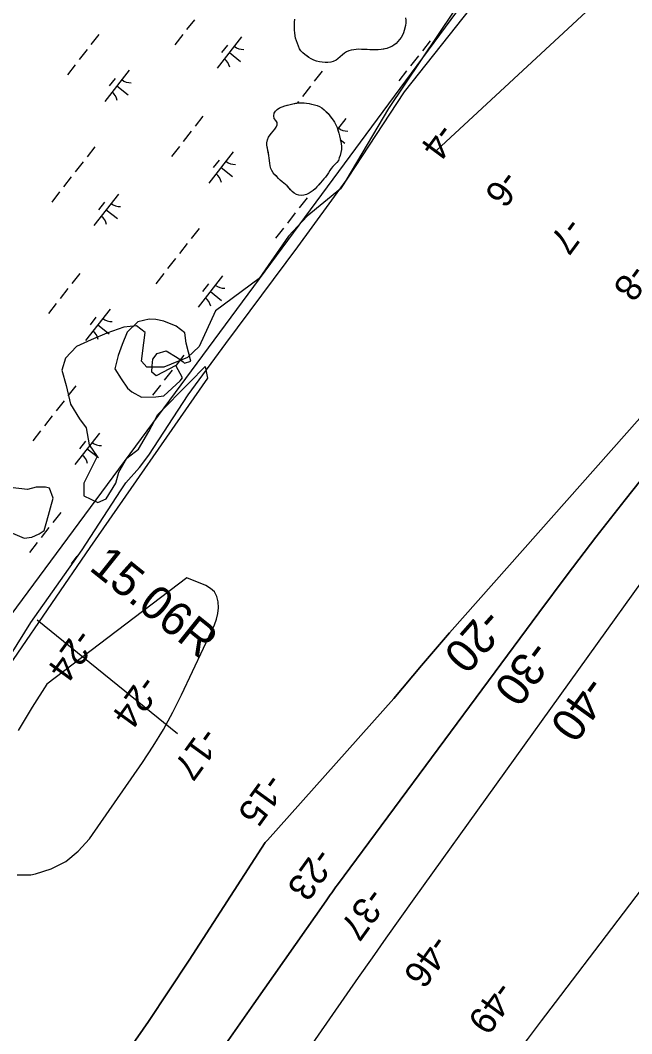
# Model space of a CAD drawing. Extents: x 3896831 to 3918110, y 171006 to 193349.
# Drawn here: x 3903450 to 3904219, y 175445 to 176718 of the extents above; entities that cross this region are included whole.
import ezdxf

# ---------------------------------------------------------------- set-up
doc = ezdxf.new("R2010")
doc.units = 0
for name, color, linetype in [('V-LEVE-TOET', 7, 'Continuous'), ('V-RIVR-EDGE', 7, 'Continuous'), ('V-RIVR-RANG', 7, 'Continuous'), ('V-RRAP-FSHR', 7, 'Continuous'), ('V-STRM-FMON', 7, 'Continuous'), ('V-TOPO-DPTH', 7, 'Continuous'), ('V-TOPO-MAJR', 7, 'Continuous'), ('V-TOPO-MINR', 7, 'Continuous'), ('V-TOPO-MINR-IDEN', 7, 'Continuous'), ('V-TOPO-SHOR', 7, 'Continuous'), ('V-WETL-SWMP', 7, 'Continuous')]:
    doc.layers.add(name, color=color, linetype=linetype)

msp = doc.modelspace()

# ---------------------------------------------------------------- linework, layer by layer
at = {"layer": 'V-LEVE-TOET'}
msp.add_line((3903471.6, 175964.8), (3903647.7, 175822), dxfattribs=at)
at = {"layer": 'V-RIVR-EDGE'}
msp.add_lwpolyline([(3904062.7, 176792.1), (3903932.6, 176627.7), (3903852.7, 176505.9), (3903810.9, 176471.6), (3903787.6, 176446.5), (3903750.5, 176393.5), (3903695.7, 176352.6), (3903675.2, 176308), (3903660.3, 176294.1), (3903630.6, 176282), (3903609.2, 176282), (3903602.7, 176289.4), (3903605.5, 176312.7), (3903607.4, 176325.7), (3903596.2, 176334), (3903580.4, 176332.2), (3903559.1, 176324.7), (3903539.5, 176316.4), (3903521, 176308), (3903507, 176293.1), (3903502.4, 176278.3), (3903508, 176258.8), (3903513.5, 176235.5), (3903524.7, 176216.9), (3903533, 176205.8), (3903536.8, 176184.4), (3903547, 176169.6), (3903530.3, 176136.1), (3903530.3, 176120.3), (3903547.9, 176111.9), (3903558.1, 176116.6), (3903570.2, 176136.1), (3903573.9, 176150), (3903584.1, 176167.7), (3903599, 176178.9), (3903612, 176201.2), (3903623.2, 176222.5), (3903663.1, 176262.5), (3903682.6, 176282.9), (3903685.4, 176268.1), (3903537.7, 176055.3), (3903392.7, 175844.3)], dxfattribs=at)
at = {"layer": 'V-RRAP-FSHR'}
msp.add_lwpolyline([(3903099, 175512.1), (3904431.1, 177312.9), (3905197.8, 178658.5), (3906088.4, 179617.4), (3906806.7, 180565.1), (3907065.2, 181039), (3907795.1, 181990.7)], dxfattribs=at)
at = {"layer": 'V-TOPO-DPTH'}
for points in [[(3903455, 175243.5), (3903504.5, 175309.5), (3903558.8, 175384.3), (3903611.2, 175460.3), (3903662.4, 175537.2), (3903758.1, 175684.8), (3903760.9, 175687.9), (3903920, 175865.9), (3903954.5, 175907.3), (3903989.7, 175948.1), (3904284.6, 176280.7)], [(3904247.5, 176161.7), (3904210.5, 176115.2), (3904173.9, 176068.3), (3904137.8, 176021), (3904102.1, 175973.5), (3903848.9, 175631.8), (3903847, 175629.3), (3903845.2, 175626.8), (3903843.4, 175624.3), (3903841.7, 175621.8), (3903839.9, 175619.2), (3903838.2, 175616.7), (3903836.4, 175614.2), (3903834.7, 175611.6), (3903744, 175482.2), (3903696.7, 175415.2), (3903649, 175348.4), (3903600.7, 175282), (3903552.1, 175215.9), (3903530.3, 175186.6)], [(3903530.3, 175186.6), (3903552.1, 175215.9), (3903600.7, 175282), (3903649, 175348.4), (3903696.7, 175415.2), (3903744, 175482.2), (3903834.7, 175611.6), (3903836.4, 175614.2), (3903838.2, 175616.7), (3903839.9, 175619.2), (3903841.7, 175621.8), (3903843.4, 175624.3), (3903845.2, 175626.8), (3903847, 175629.3), (3903848.9, 175631.8), (3904102.1, 175973.5), (3904137.8, 176021), (3904173.9, 176068.3), (3904210.5, 176115.2), (3904247.5, 176161.7)], [(3904255.6, 176046.2), (3903945, 175614.1), (3903927.4, 175589.5), (3903909.8, 175564.8), (3903892.4, 175540), (3903875.1, 175515.2), (3903774.4, 175370.4), (3903726.9, 175302.4), (3903679.2, 175234.5), (3903631.3, 175166.8), (3903605.2, 175130.1)], [(3904255.6, 176046.2), (3903945, 175614.1), (3903927.4, 175589.5), (3903909.8, 175564.8), (3903892.4, 175540), (3903875.1, 175515.2), (3903774.4, 175370.4), (3903726.9, 175302.4), (3903679.2, 175234.5), (3903631.3, 175166.8), (3903605.2, 175130.1)], [(3903446.5, 175644.4), (3903463.4, 175644.4), (3903469.2, 175645.5), (3903489.2, 175651.9), (3903507.5, 175661), (3903523.1, 175674), (3903537.1, 175689.7), (3903603.8, 175785.3), (3903617.4, 175805.9), (3903630.3, 175826.8), (3903642, 175848.5), (3903653, 175870.5), (3903694.3, 175958.5), (3903696.8, 175965.4), (3903698.6, 175972.5), (3903699.3, 175979.7), (3903699.1, 175987.1), (3903697.2, 175993.8), (3903694.2, 175999.6), (3903689.5, 176004.1), (3903683.6, 176007.7), (3903659.5, 176017.4), (3903483.6, 175883.8)], [(3903483.6, 175883.8), (3903465.1, 175854.9), (3903447.6, 175825.4)]]:
    msp.add_lwpolyline(points, dxfattribs=at)
at = {"layer": 'V-TOPO-MAJR'}
msp.add_lwpolyline([(3904246.5, 175647), (3904193.6, 175577.1), (3904122.8, 175484.1), (3904105.1, 175460.8), (3904087.4, 175437.6), (3904069.6, 175414.4), (3904051.8, 175391.3), (3903932.4, 175236.1), (3903882.7, 175172), (3903832.8, 175108.1), (3903782.5, 175044.5), (3903758.5, 175014.3)], dxfattribs=at)
at = {"layer": 'V-TOPO-MINR'}
for points in [[(3904260.2, 176827.7), (3904201.3, 176765.7), (3903973.7, 176554.7)], [(3904284.6, 176280.7), (3903989.7, 175948.1), (3903954.5, 175907.3), (3903920, 175865.9), (3903760.9, 175687.9), (3903758.1, 175684.8), (3903662.4, 175537.2), (3903611.2, 175460.3), (3903558.8, 175384.3), (3903504.5, 175309.5), (3903455, 175243.5)], [(3904247.5, 176161.7), (3904210.5, 176115.2), (3904173.9, 176068.3), (3904137.8, 176021), (3904102.1, 175973.5), (3903848.9, 175631.8), (3903847, 175629.3), (3903845.2, 175626.8), (3903843.4, 175624.3), (3903841.7, 175621.8), (3903839.9, 175619.2), (3903838.2, 175616.7), (3903836.4, 175614.2), (3903834.7, 175611.6), (3903744, 175482.2), (3903696.7, 175415.2), (3903649, 175348.4), (3903600.7, 175282), (3903552.1, 175215.9), (3903530.3, 175186.6)], [(3904255.6, 176046.2), (3903945, 175614.1), (3903927.4, 175589.5), (3903909.8, 175564.8), (3903892.4, 175540), (3903875.1, 175515.2), (3903774.4, 175370.4), (3903726.9, 175302.4), (3903679.2, 175234.5), (3903631.3, 175166.8), (3903605.2, 175130.1)], [(3903446.5, 175644.4), (3903463.4, 175644.4), (3903469.2, 175645.5), (3903489.2, 175651.9), (3903507.5, 175661), (3903523.1, 175674), (3903537.1, 175689.7), (3903603.8, 175785.3), (3903617.4, 175805.9), (3903630.3, 175826.8), (3903642, 175848.5), (3903653, 175870.5), (3903694.3, 175958.5), (3903696.8, 175965.4), (3903698.6, 175972.5), (3903699.3, 175979.7), (3903699.1, 175987.1), (3903697.2, 175993.8), (3903694.2, 175999.6), (3903689.5, 176004.1), (3903683.6, 176007.7), (3903659.5, 176017.4), (3903483.6, 175883.8)], [(3903483.6, 175883.8), (3903465.1, 175854.9), (3903447.6, 175825.4)]]:
    msp.add_lwpolyline(points, dxfattribs=at)
at = {"layer": 'V-TOPO-SHOR'}
for points in [[(3903797.6, 176691.7), (3903796.4, 176695), (3903795.7, 176698.3), (3903795.5, 176701.7), (3903795.1, 176705.2), (3903795, 176708.3), (3903794.8, 176711.7), (3903795, 176715.5), (3903795.4, 176718.9)], [(3903934.6, 176720.7), (3903934.8, 176717.6), (3903934.8, 176714.3), (3903934.4, 176711.2), (3903933.6, 176708), (3903932.9, 176705), (3903931.9, 176702), (3903930.6, 176698.8), (3903929, 176696.2), (3903927.1, 176693.5), (3903924.7, 176690.9), (3903922.6, 176688.5), (3903920, 176686.3), (3903917.3, 176684.8), (3903914.1, 176683.4), (3903911, 176682.3), (3903907.1, 176681.5), (3903903.9, 176680.9), (3903900.1, 176680.7), (3903897, 176680.6), (3903893.3, 176680.6), (3903889.7, 176680.6), (3903886.4, 176680.8), (3903883, 176680.9), (3903879.3, 176681.1), (3903876, 176681.2), (3903872.6, 176681), (3903869.4, 176680.6), (3903866.3, 176680.1), (3903863.3, 176679.1), (3903860.4, 176677.9), (3903857.8, 176676.3), (3903855.1, 176674.3)], [(3903855.1, 176674.3), (3903852.4, 176671.8), (3903849.6, 176669.3), (3903847.2, 176667.5), (3903843.7, 176665.8), (3903840.7, 176665), (3903836.8, 176664.6), (3903833.7, 176664.5), (3903829.6, 176664.9), (3903826.3, 176665.5), (3903822.5, 176666.5), (3903819.3, 176667.6), (3903816, 176669.1), (3903813.1, 176670.8), (3903810.4, 176672.8), (3903807.9, 176674.8), (3903805.3, 176676.9), (3903803.1, 176679.2), (3903801.4, 176681.6), (3903797.6, 176691.7)], [(3903779.5, 176514.9), (3903777.1, 176517), (3903774.9, 176519.1), (3903772.6, 176521.3), (3903770.3, 176523.4), (3903768.3, 176526), (3903766.5, 176528.8), (3903765.2, 176531.6), (3903764.4, 176534.7), (3903763.9, 176538.1), (3903763.6, 176541.4), (3903763.3, 176544.5), (3903762.8, 176548), (3903762.2, 176551.2), (3903761.5, 176554.1), (3903760.8, 176557.5), (3903760.2, 176560.6), (3903760.3, 176563.8), (3903760.9, 176567.3), (3903762.4, 176570.8), (3903764.2, 176573.7), (3903766.1, 176576), (3903768.2, 176578.3), (3903770.2, 176580.8), (3903771.8, 176583.4), (3903773, 176586.2), (3903773, 176589.3), (3903771.4, 176591.9), (3903769.5, 176594.5), (3903768.9, 176597.6), (3903769.5, 176600.8), (3903771.1, 176603.4), (3903773.3, 176605.7), (3903776, 176607.5), (3903779.6, 176609), (3903782.8, 176610.2), (3903785.7, 176611), (3903789.3, 176612), (3903792.8, 176612.8), (3903796.3, 176613.4), (3903800.3, 176614), (3903803.6, 176614.1), (3903806.9, 176614), (3903810.2, 176613.6), (3903813.2, 176613.1), (3903816.3, 176612.4), (3903820.1, 176611.5), (3903823.3, 176610.5), (3903826.3, 176609.3), (3903829.3, 176607.5), (3903832.2, 176605.3), (3903834.8, 176602.8), (3903837.1, 176600.6), (3903839.3, 176597.8), (3903841.6, 176594.7), (3903843.5, 176592.3), (3903845.4, 176589.5), (3903847.1, 176586.2), (3903848.4, 176582.9), (3903849.5, 176579.6), (3903850.7, 176575.8), (3903851.6, 176572.4), (3903852.2, 176569.1), (3903852.8, 176566.1), (3903853.4, 176562.8), (3903853.9, 176559.3), (3903853.9, 176555.4), (3903853.1, 176551.4), (3903852.4, 176547.9), (3903851.3, 176544.7), (3903850.1, 176541.7), (3903848.2, 176539), (3903845.7, 176536.6), (3903843.3, 176534.1), (3903840.9, 176531.4), (3903839.2, 176528.9), (3903837.6, 176526.1), (3903835.8, 176523.5), (3903833.8, 176520.7), (3903831.9, 176518.4), (3903829.9, 176515.9), (3903827.7, 176513.4), (3903825.5, 176511.1), (3903823.1, 176508.5), (3903820.9, 176506.1), (3903818.4, 176503.9), (3903816.1, 176502), (3903813.4, 176500.3), (3903809.9, 176498.7), (3903806.7, 176497.9), (3903803.6, 176497.5), (3903800.5, 176497.8), (3903797.5, 176498.7), (3903794.6, 176500.5), (3903792.1, 176502.6), (3903789.8, 176504.9), (3903787.8, 176507.2), (3903785.6, 176509.6), (3903779.5, 176514.9)]]:
    msp.add_lwpolyline(points, dxfattribs=at)
for points in [[(3903664.6, 176289.7), (3903658.6, 176311.9), (3903657.1, 176324.9), (3903646.2, 176333.4), (3903630.6, 176339.7), (3903620.5, 176341.8), (3903612.2, 176342.4), (3903597.9, 176339), (3903584.7, 176326), (3903578.3, 176310.4), (3903573.4, 176296.7), (3903568.9, 176279.7), (3903577, 176267.5), (3903585, 176255.4), (3903590.4, 176251.1), (3903602.8, 176244.4), (3903620.8, 176244.9), (3903630.5, 176246.1), (3903651.2, 176265), (3903654, 176268.7), (3903645.6, 176284.1), (3903620.9, 176271.2), (3903615.4, 176275.5), (3903616.1, 176283.8), (3903616.7, 176292.1), (3903622.4, 176299.3), (3903633.5, 176302.3), (3903647.6, 176294.2), (3903654.9, 176288.5), (3903656.7, 176287.1)], [(3903483.7, 176088.7), (3903491.7, 176117.6), (3903486.8, 176130.1), (3903481.8, 176131.2), (3903470.3, 176131.4), (3903459.1, 176128.4), (3903437.5, 176130.7), (3903423.8, 176135.6), (3903414, 176134.4), (3903397.6, 176120.9), (3903398.8, 176111.2), (3903418.8, 176095.6), (3903428.2, 176085.2), (3903437.7, 176074.9), (3903455.1, 176067.1), (3903464.8, 176068.3), (3903474.1, 176072.7), (3903480.2, 176076.8)]]:
    msp.add_lwpolyline(points, close=True, dxfattribs=at)
at = {"layer": 'V-WETL-SWMP'}
for p, q in [((3903913.5, 176606.7), (3903995.8, 176728.9)), ((3903669.2, 176718.4), (3903659.3, 176705.9)), ((3903794.8, 176711.7), (3903795, 176715.5)), ((3903795.1, 176705.2), (3903794.8, 176711.7)), ((3903795, 176715.5), (3903795.4, 176718.9)), ((3903934.4, 176711.2), (3903932.9, 176705)), ((3903934.8, 176714.3), (3903934.4, 176711.2)), ((3903934.6, 176720.7), (3903934.8, 176717.6)), ((3903934.8, 176717.6), (3903934.8, 176714.3)), ((3903548.9, 176699.7), (3903539, 176687.1)), ((3903654.4, 176699.6), (3903644.5, 176687)), ((3903795.5, 176701.7), (3903795.1, 176705.2)), ((3903795.7, 176698.3), (3903795.5, 176701.7)), ((3903796.4, 176695), (3903795.7, 176698.3)), ((3903930.6, 176698.8), (3903929, 176696.2)), ((3903931.9, 176702), (3903930.6, 176698.8)), ((3903932.9, 176705), (3903931.9, 176702)), ((3903728.5, 176696.8), (3903697.6, 176657.5)), ((3903710.7, 176686.6), (3903703.3, 176677.2)), ((3903797.6, 176691.7), (3903796.4, 176695)), ((3903801.3, 176681.6), (3903797.6, 176691.7)), ((3903917.3, 176684.8), (3903914.1, 176683.4)), ((3903920, 176686.3), (3903917.3, 176684.8)), ((3903922.6, 176688.5), (3903920, 176686.3)), ((3903927.1, 176693.5), (3903922.6, 176688.5)), ((3903929, 176696.2), (3903927.1, 176693.5)), ((3903965.5, 176692), (3903955.7, 176679.4)), ((3903534.1, 176680.8), (3903524.2, 176668.2)), ((3903713.1, 176677.1), (3903727.2, 176666)), ((3903803.1, 176679.2), (3903801.3, 176681.6)), ((3903805.3, 176676.9), (3903803.1, 176679.2)), ((3903807.9, 176674.8), (3903805.3, 176676.9)), ((3903813.1, 176670.8), (3903807.9, 176674.8)), ((3903855.1, 176674.3), (3903849.6, 176669.3)), ((3903857.8, 176676.3), (3903855.1, 176674.3)), ((3903860.4, 176677.9), (3903857.8, 176676.3)), ((3903863.3, 176679.1), (3903860.4, 176677.9)), ((3903866.3, 176680.1), (3903863.3, 176679.1)), ((3903869.4, 176680.6), (3903866.3, 176680.1)), ((3903872.6, 176681), (3903869.4, 176680.6)), ((3903876, 176681.2), (3903872.6, 176681)), ((3903886.4, 176680.8), (3903876, 176681.2)), ((3903889.7, 176680.6), (3903886.4, 176680.8)), ((3903897, 176680.6), (3903889.7, 176680.6)), ((3903903.9, 176680.9), (3903897, 176680.6)), ((3903911, 176682.3), (3903903.9, 176680.9)), ((3903914.1, 176683.4), (3903911, 176682.3)), ((3903950.7, 176673.1), (3903940.9, 176660.5)), ((3903519.3, 176661.9), (3903509.4, 176649.3)), ((3903816, 176669.1), (3903813.1, 176670.8)), ((3903819.3, 176667.6), (3903816, 176669.1)), ((3903822.5, 176666.5), (3903819.3, 176667.6)), ((3903826.3, 176665.5), (3903822.5, 176666.5)), ((3903829.6, 176664.9), (3903826.3, 176665.5)), ((3903833.7, 176664.5), (3903829.6, 176664.9)), ((3903836.8, 176664.6), (3903833.7, 176664.5)), ((3903840.7, 176665), (3903836.8, 176664.6)), ((3903843.7, 176665.8), (3903840.7, 176665)), ((3903847.2, 176667.5), (3903843.7, 176665.8)), ((3903849.6, 176669.3), (3903847.2, 176667.5)), ((3903587.1, 176654.9), (3903556.3, 176615.5)), ((3903829.7, 176653.6), (3903819.8, 176641)), ((3903935.9, 176654.2), (3903926.1, 176641.6)), ((3903569.3, 176644.7), (3903561.9, 176635.2)), ((3903571.7, 176635.2), (3903585.8, 176624.1)), ((3903814.9, 176634.7), (3903805, 176622.1)), ((3903776, 176607.5), (3903779.6, 176609)), ((3903779.6, 176609), (3903782.8, 176610.2)), ((3903782.8, 176610.2), (3903789.3, 176612)), ((3903789.3, 176612), (3903792.8, 176612.8)), ((3903792.8, 176612.8), (3903800.3, 176614)), ((3903800.1, 176615.8), (3903798.4, 176613.7)), ((3903800.3, 176614), (3903803.6, 176614.1)), ((3903803.6, 176614.1), (3903806.9, 176614)), ((3903806.9, 176614), (3903810.2, 176613.6)), ((3903810.2, 176613.6), (3903813.2, 176613.1)), ((3903813.2, 176613.1), (3903820.1, 176611.5)), ((3903820.1, 176611.5), (3903823.3, 176610.5)), ((3903823.3, 176610.5), (3903826.3, 176609.3)), ((3903826.3, 176609.3), (3903829.3, 176607.5)), ((3903679.8, 176597.1), (3903669.9, 176584.5)), ((3903768.9, 176597.6), (3903769.5, 176600.8)), ((3903769.5, 176594.5), (3903768.9, 176597.6)), ((3903769.5, 176600.8), (3903771.1, 176603.4)), ((3903771.1, 176603.4), (3903773.3, 176605.7)), ((3903773.3, 176605.7), (3903776, 176607.5)), ((3903829.3, 176607.5), (3903832.2, 176605.3)), ((3903832.2, 176605.3), (3903837.1, 176600.6)), ((3903837.1, 176600.6), (3903839.3, 176597.8)), ((3903839.3, 176597.8), (3903843.5, 176592.3)), ((3903859.7, 176516.5), (3903913.5, 176606.7)), ((3903771.4, 176591.9), (3903769.5, 176594.5)), ((3903770.2, 176580.8), (3903771.8, 176583.4)), ((3903773, 176589.3), (3903771.4, 176591.9)), ((3903771.8, 176583.4), (3903773, 176586.2)), ((3903773, 176586.2), (3903773, 176589.3)), ((3903843.5, 176592.3), (3903845.4, 176589.5)), ((3903845.4, 176589.5), (3903847.1, 176586.2)), ((3903847.1, 176586.2), (3903848.4, 176582.9)), ((3903848.4, 176582.9), (3903850.7, 176575.8)), ((3903859.4, 176594.2), (3903849, 176580.9)), ((3903665, 176578.2), (3903655.1, 176565.6)), ((3903760.9, 176567.3), (3903762.4, 176570.8)), ((3903762.4, 176570.8), (3903764.2, 176573.7)), ((3903764.2, 176573.7), (3903766.1, 176576)), ((3903766.1, 176576), (3903768.2, 176578.3)), ((3903768.2, 176578.3), (3903770.2, 176580.8)), ((3903850.7, 176575.8), (3903851.6, 176572.4)), ((3903851.6, 176572.4), (3903853.4, 176562.8)), ((3903544, 176558.7), (3903534.1, 176546.1)), ((3903650.2, 176559.3), (3903640.3, 176546.7)), ((3903760.2, 176560.6), (3903760.3, 176563.8)), ((3903762.8, 176548), (3903760.2, 176560.6)), ((3903760.3, 176563.8), (3903760.9, 176567.3)), ((3903852.5, 176567.9), (3903858.1, 176563.4)), ((3903853.4, 176562.8), (3903853.9, 176559.3)), ((3903853.9, 176559.3), (3903853.9, 176555.4)), ((3903718, 176552.3), (3903687.2, 176512.9)), ((3903763.3, 176544.5), (3903762.8, 176548)), ((3903763.9, 176538.1), (3903763.3, 176544.5)), ((3903851.3, 176544.7), (3903850.1, 176541.7)), ((3903852.4, 176547.9), (3903851.3, 176544.7)), ((3903853.9, 176555.4), (3903852.4, 176547.9)), ((3903529.2, 176539.8), (3903519.3, 176527.2)), ((3903700.2, 176542.1), (3903692.8, 176532.6)), ((3903702.6, 176532.6), (3903716.8, 176521.5)), ((3903764.4, 176534.7), (3903763.9, 176538.1)), ((3903765.2, 176531.6), (3903764.4, 176534.7)), ((3903843.3, 176534.1), (3903840.9, 176531.4)), ((3903848.2, 176539), (3903843.3, 176534.1)), ((3903850.1, 176541.7), (3903848.2, 176539)), ((3903514.3, 176520.9), (3903504.5, 176508.3)), ((3903766.5, 176528.8), (3903765.2, 176531.6)), ((3903768.3, 176526), (3903766.5, 176528.8)), ((3903770.3, 176523.4), (3903768.3, 176526)), ((3903777.1, 176517), (3903770.3, 176523.4)), ((3903833.8, 176520.7), (3903831.9, 176518.4)), ((3903837.6, 176526.1), (3903833.8, 176520.7)), ((3903839.2, 176528.9), (3903837.6, 176526.1)), ((3903840.9, 176531.4), (3903839.2, 176528.9)), ((3903779.5, 176514.9), (3903777.1, 176517)), ((3903785.6, 176509.6), (3903779.5, 176514.9)), ((3903792.1, 176502.6), (3903785.6, 176509.6)), ((3903799, 176433), (3903859.7, 176516.5)), ((3903823.1, 176508.5), (3903820.9, 176506.1)), ((3903827.7, 176513.4), (3903823.1, 176508.5)), ((3903829.9, 176515.9), (3903827.7, 176513.4)), ((3903831.9, 176518.4), (3903829.9, 176515.9)), ((3903499.5, 176502), (3903489.7, 176489.4)), ((3903573.7, 176499.3), (3903542.8, 176460)), ((3903794.6, 176500.5), (3903792.1, 176502.6)), ((3903797.5, 176498.7), (3903794.6, 176500.5)), ((3903800.5, 176497.8), (3903797.5, 176498.7)), ((3903803.6, 176497.5), (3903800.5, 176497.8)), ((3903810.7, 176494.5), (3903800.9, 176481.9)), ((3903806.7, 176497.9), (3903803.6, 176497.5)), ((3903809.9, 176498.7), (3903806.7, 176497.9)), ((3903813.4, 176500.3), (3903809.9, 176498.7)), ((3903816.1, 176502), (3903813.4, 176500.3)), ((3903818.4, 176503.9), (3903816.1, 176502)), ((3903820.9, 176506.1), (3903818.4, 176503.9)), ((3903555.9, 176489.1), (3903548.5, 176479.7)), ((3903558.3, 176479.6), (3903572.4, 176468.5)), ((3903795.9, 176475.6), (3903786, 176463)), ((3903674.9, 176456.1), (3903665, 176443.5)), ((3903781.1, 176456.7), (3903771.2, 176444.1)), ((3903660.1, 176437.2), (3903650.2, 176424.6)), ((3903708.7, 176311.5), (3903799, 176433)), ((3903645.3, 176418.3), (3903635.4, 176405.7)), ((3903525, 176399.6), (3903515.1, 176387)), ((3903630.5, 176399.4), (3903620.6, 176386.8)), ((3903704.6, 176396.7), (3903673.8, 176357.3)), ((3903510.2, 176380.7), (3903500.3, 176368.1)), ((3903686.8, 176386.5), (3903679.4, 176377.1)), ((3903689.2, 176377), (3903703.3, 176365.9)), ((3903495.4, 176361.8), (3903485.5, 176349.2)), ((3903563.2, 176354.7), (3903532.4, 176315.4)), ((3903545.4, 176344.6), (3903538, 176335.1)), ((3903547.8, 176335.1), (3903562, 176324)), ((3903661.2, 176247.3), (3903708.7, 176311.5)), ((3903655.9, 176297), (3903646, 176284.4)), ((3903655.9, 176297), (3903651.4, 176291.2)), ((3903641.1, 176278.1), (3903631.2, 176265.5)), ((3903641.1, 176278.1), (3903631.2, 176265.5)), ((3903520.1, 176258.6), (3903510.2, 176246)), ((3903626.3, 176259.2), (3903616.4, 176246.6)), ((3903626.3, 176259.2), (3903616.4, 176246.6)), ((3903505.3, 176239.7), (3903495.4, 176227.1)), ((3903612, 176171.5), (3903661.2, 176247.3)), ((3903490.5, 176220.8), (3903480.6, 176208.2)), ((3903475.7, 176201.9), (3903465.8, 176189.3)), ((3903549.8, 176199.2), (3903518.9, 176159.8)), ((3903532, 176189), (3903524.6, 176179.5)), ((3903534.4, 176179.5), (3903548.5, 176168.4)), ((3903600, 176156), (3903612, 176171.5)), ((3903582.7, 176136.7), (3903600, 176156)), ((3903527.9, 176052.6), (3903576.1, 176126.6)), ((3903576.1, 176126.6), (3903582.7, 176136.7)), ((3903501.1, 176099.4), (3903491.2, 176086.8)), ((3903486.3, 176080.5), (3903476.4, 176068)), ((3903471.5, 176061.7), (3903461.6, 176049.1)), ((3903463.3, 175961.3), (3903527.9, 176052.6)), ((3903521.5, 176044.4), (3903514.1, 176035)), ((3903417.4, 175887.6), (3903463.3, 175961.3))]:
    msp.add_line(p, q, dxfattribs=at)
for points in [[(3903664.6, 176289.7), (3903658.6, 176311.9), (3903657.1, 176324.9), (3903646.2, 176333.4), (3903630.6, 176339.7), (3903620.5, 176341.8), (3903612.2, 176342.4), (3903597.9, 176339), (3903584.7, 176326), (3903578.3, 176310.4), (3903573.4, 176296.7), (3903568.9, 176279.7), (3903577, 176267.5), (3903585, 176255.4), (3903590.4, 176251.1), (3903602.8, 176244.4), (3903620.8, 176244.9), (3903630.5, 176246.1), (3903651.2, 176265), (3903654, 176268.7), (3903645.6, 176284.1), (3903620.9, 176271.2), (3903615.4, 176275.5), (3903616.1, 176283.8), (3903616.7, 176292.1), (3903622.4, 176299.3), (3903633.5, 176302.3), (3903647.6, 176294.2), (3903654.9, 176288.5), (3903656.7, 176287.1)], [(3903483.7, 176088.7), (3903491.7, 176117.6), (3903486.8, 176130.1), (3903481.8, 176131.2), (3903470.3, 176131.4), (3903459.1, 176128.4), (3903437.5, 176130.7), (3903423.8, 176135.6), (3903414, 176134.4), (3903397.6, 176120.9), (3903398.8, 176111.2), (3903418.8, 176095.6), (3903428.2, 176085.2), (3903437.7, 176074.9), (3903455.1, 176067.1), (3903464.8, 176068.3), (3903474.1, 176072.7), (3903480.2, 176076.8)]]:
    msp.add_lwpolyline(points, close=True, dxfattribs=at)
for centre, start, end in [((3903730.3, 176698.7), 231.1403, 272.6839), ((3903696.2, 176655.3), 11.1403, 52.6839), ((3903588.9, 176656.8), 231.1403, 272.6839), ((3903554.8, 176613.3), 11.1403, 52.6839), ((3903861.2, 176596.1), 231.1403, 272.6839), ((3903719.8, 176554.2), 231.1403, 272.6839), ((3903685.7, 176510.7), 11.1403, 52.6839), ((3903575.5, 176501.2), 231.1403, 272.6839), ((3903541.4, 176457.7), 11.1403, 52.6839), ((3903706.4, 176398.6), 231.1403, 272.6839), ((3903672.3, 176355.1), 11.1403, 52.6839), ((3903565, 176356.7), 231.1403, 272.6839), ((3903530.9, 176313.2), 11.1403, 52.6839), ((3903551.6, 176201.1), 231.1403, 272.6839), ((3903517.5, 176157.6), 11.1403, 52.6839)]:
    msp.add_arc(centre, 17.6, start, end, dxfattribs=at)

# ---------------------------------------------------------------- texts
at = {"layer": 'V-RIVR-RANG'}
for s, rotation, p in [('-4', 233.5583, (3903975.8, 176590.9)), ('-6', 233.5583, (3904056.4, 176531.8)), ('-7', 233.5583, (3904137, 176472.6)), ('-8', 233.5583, (3904217.8, 176413.7)), ('-24', 234.0783, (3903521.2, 175955.8)), ('-24', 234.0783, (3903602.3, 175897.4)), ('-17', 234.0783, (3903678.6, 175832.2)), ('-15', 234.0783, (3903760.2, 175774.4)), ('-23', 234.2226, (3903822.2, 175680.9)), ('-37', 234.2226, (3903887.6, 175630.9)), ('-46', 234.2226, (3903968.5, 175571.6)), ('-49', 234.2226, (3904049.3, 175513.2))]:
    msp.add_text(s, height=33.5, rotation=rotation, dxfattribs=at).set_placement(p)
at = {"layer": 'V-STRM-FMON'}
msp.add_text('15.06R', height=42, rotation=321.2799, dxfattribs=at).set_placement((3903535.4, 176028.1))
at = {"layer": 'V-TOPO-MINR-IDEN'}
for s, rotation, p in [('-20', 228.4432, (3904033.5, 175981.9)), ('-30', 233.4489, (3904091.6, 175941.9)), ('-40', 234.2859, (3904161.3, 175897.2))]:
    msp.add_text(s, height=41.5, rotation=rotation, dxfattribs=at).set_placement(p)

doc.saveas('drawing.dxf')
